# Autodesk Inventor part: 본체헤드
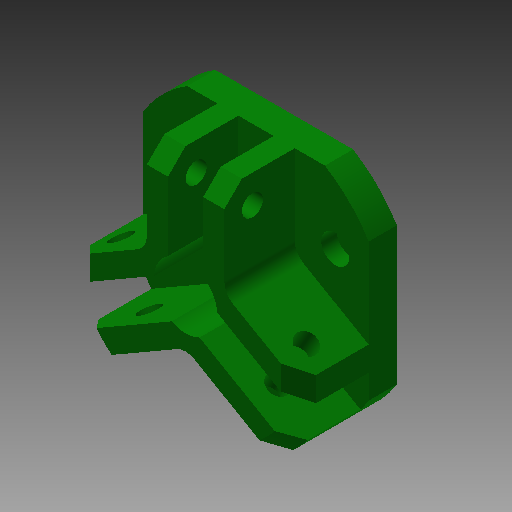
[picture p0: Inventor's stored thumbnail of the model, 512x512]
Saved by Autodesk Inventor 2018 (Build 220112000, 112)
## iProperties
Created: 2020-02
Part Number: 본체헤드
Material: 알루미늄 6061
Document SubType Name: Modeling
Designer: mduedu
Density: 1 g/cm^3
Appearance: 진녹색
Author: mduedu
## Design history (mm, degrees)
sketch "스케치1"
  geometry: L1 (-32, -32)-(32, -32); L2 (32, -32)-(32, 32); L3 (32, 32)-(-32, 32); L4 (-32, 32)-(-32, -32); L5 (-32, -32)-(32, 32); L6 (32, -32)-(-32, 32); 1 further point
  constraints: 12 end point, 2 midpoint, 2 parallel, 1 horizontal, 1 perpendicular
  dimensions: "d0" = 64 distance of L3.end L2.end; "d1" = 64 distance of L2.end L1.end
extrude "돌출1" new body sketch "스케치1" distance "d2" = 28; taper "d3" = 0 deg
sketch "스케치2"
  geometry: C1 r 37.5 at (0, 0); 1 further point
  constraints: 1 centre point, 1 coincident
  dimensions: "d4" = 75 diameter of C1
extrude "돌출2" sketch "스케치2" stored distance "d5" = 28; taper "d6" = 0 deg
sketch "스케치3"
  geometry: C1 r 20 at (0, 0); 1 further point
  constraints: 1 centre point, 1 coincident
  dimensions: "d7" = 40 diameter of C1
extrude "돌출3" join sketch "스케치3" distance "d8" = 12; taper "d9" = 0 deg
sketch "스케치4"
  geometry: L1 (-32, 19.551)-(-32, -19.551) reference; L2 (-19.551, -32)-(19.551, -32) reference; L3 (32, -19.551)-(32, 19.551) reference; L4 (19.551, 32)-(-19.551, 32) reference; L5 (0, 0)-(0, 37.5); L6 (0, 0)-(32.476, -18.75); L7 (0, 0)-(-32.476, -18.75); L8 (11, 6.351)-(11, 35.85); L9 (-11, 6.351)-(-11, 35.85); L10 (-11, 6.351)-(-36.547, -8.399); L11 (0, -12.702)-(-25.547, -27.451); L12 (11, 6.351)-(36.547, -8.399); L13 (0, -12.702)-(25.547, -27.451); L14 (-5, 2.887)-(-5, 37.165); L15 (5, 2.887)-(5, 37.165); L16 (-5, 2.887)-(-34.686, -14.252); L17 (0, -5.774)-(-29.686, -22.913); L18 (0, -5.774)-(29.686, -22.913); L19 (5, 2.887)-(34.686, -14.252); A1 r 37.5 centre (0, 0) between (-19.551, 32) and (-32, 19.551) reference; A2 r 37.5 centre (0, 0) between (-32, -19.551) and (-19.551, -32) reference; A3 r 37.5 centre (0, 0) between (19.551, -32) and (32, -19.551) reference; A4 r 37.5 centre (0, 0) between (32, 19.551) and (19.551, 32) reference; 1 further point
  constraints: 30 end point, 12 parallel, 2 point on circle, 1 coincident, 1 perpendicular, 24 other
  dimensions: "d10" = 120 deg angle of L6 L5; "d11" = 120 deg angle of L7 L6; "d12" = 22 distance between parallel lines of L8 L9; "d14" = 22 distance between parallel lines of L11 L10; "d15" = 22 distance between parallel lines of L12 L13; "d18" = 10 distance between parallel lines of L15 L14; "d19" = 10 distance between parallel lines of L18 L19; "d20" = 10 distance between parallel lines of L16 L17
  node "투영된 루프1"
extrude "돌출4" cut sketch "스케치4" distance "d16" = 20; taper "d17" = 0 deg
extrude "돌출5" cut sketch "스케치4" distance "d21" = 20; taper "d22" = 0 deg
sketch "스케치5"
  geometry: C1 r 9 at (0, 0); 1 further point
  constraints: 1 centre point, 1 coincident
  dimensions: "d23" = 18 diameter of C1
extrude "돌출6" cut sketch "스케치5" extent not by distance; stored distance "d24" = 20; taper "d25" = 0 deg
sketch "스케치6"
  geometry: L1 (32, 0)-(19.551, 0) reference; C1 r 3 at (24, 20); 1 further point
  constraints: 1 centre point
  dimensions: "d26" = 6 diameter of C1; "d27" = 24 horizontal distance of C1.centre point (0, 0); "d28" = 20 distance from line of C1.centre L1
extrude "돌출7" cut sketch "스케치6" extent not by distance; stored distance "d29" = 20; taper "d30" = 0 deg
sketch "스케치7"
  geometry: L1 (-20, -12)-(-20, 0) reference; L2 (-20, 0)-(-32, 0) reference; L3 (-32, 0)-(-32, 8) reference; L4 (-32, 8)-(-12.702, 8) reference; L5 (-12.702, 8)-(-12.702, 28) reference; L6 (-12.702, 28)-(-9, 28) reference; L7 (-9, 28)-(-9, -12) reference; L8 (-9, -12)-(-20, -12) reference; L9 (20, 0)-(20, -12) reference; L10 (20, -12)-(9, -12) reference; L11 (9, -12)-(9, 8) reference; L12 (9, 8)-(32, 8) reference; L13 (32, 8)-(32, 0) reference; L14 (32, 0)-(20, 0) reference; L15 (20, -8.35)-(17, -8.35); L16 (17, -8.35)-(17, -3.65); L17 (17, -3.65)-(20, -3.65); L18 (20, -3.65)-(20, -8.35); L19 (9, -2.4)-(11, -2.4); L20 (11, -2.4)-(11, -5.6); L21 (11, -5.6)-(9, -5.6); L22 (9, -5.6)-(9, -2.4); L23 (0, -20)-(0, 36) reference; L24 (17, -6)-(20, -6); L25 (11, -4)-(9, -4); 1 further point
  constraints: 20 end point, 4 midpoint, 4 parallel, 2 horizontal, 2 perpendicular, 2 point on line
  dimensions: "d34" = 6 distance between parallel lines of L24 L14; "d35" = 34 diameter of L16 L23; "d36" = 4.7 distance between parallel lines of L17 L15; "d37" = 8 distance between parallel lines of L25 L10; "d38" = 3.2 distance of L19.end L20.end; "d39" = 22 diameter of L20 L23
revolve "회전1" sketch "스케치7" stored, may be unused: angle "d40" = 90 deg
fillet "모깎기1" dims "d41" = 0.8
fillet "모깎기2" dims "d42" = 0.4
chamfer "모따기1" distance "d43" = 0.3; stored, may be unused: second distance "d44" = 2, angle "d45" = 45 deg
chamfer "모따기2" distance "d46" = 0.3; stored, may be unused: second distance "d47" = 2, angle "d48" = 45 deg
chamfer "모따기3" distance "d49" = 1; stored, may be unused: second distance "d50" = 2, angle "d51" = 45 deg
fillet "모깎기3" dims "d52" = 5
chamfer "모따기4" distance "d53" = 5; stored, may be unused: second distance "d54" = 2, angle "d55" = 45 deg
sketch "스케치8" dims "d56" = 52
  geometry: 3 further points
  constraints: 2 vertical alignment, 1 coincident, 2 other
hole "구멍1" sketch "스케치8" at (0, -26) diameter "d57" = 4.5; stored, may be unused: countersink angle "d61" = 90 deg, drill point angle "d63" = 118 deg; dims "d58" = 6, "d59" = 8, "d60" = 4.4, "d62" = 8
node "작업 평면1"
node "작업 평면2"
node "솔리드1"
pattern_circular "원형 패턴1" dims angle "d32" = 360 deg
pattern_circular "원형 패턴2" dims angle "d65" = 360 deg
node "절단 모서리 투영1"
